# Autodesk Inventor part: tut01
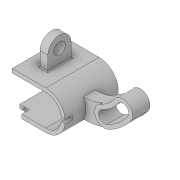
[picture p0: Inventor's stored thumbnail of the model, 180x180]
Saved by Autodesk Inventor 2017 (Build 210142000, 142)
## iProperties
Created: 2015-03
Part Number: tut01
Material: Generic
Document SubType Name: Modeling
Designer: Sandeep
Density: 1 g/cm^3
Appearance: Default
Author: Sandeep
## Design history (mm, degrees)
sketch "Sketch1"
  geometry: L1 (35, 20)-(0, 20); L2 (0, -20)-(35, -20); L3 (35, 16)-(0, 16); L4 (0, -16)-(35, -16); L5 (35, 16)-(35, 20); L6 (35, -16)-(35, -20); L7 (42.148, 0)-(-37.683, 0); A1 r 20 centre (0, 0) between (0, 20) and (0, -20); A2 r 16 centre (0, 0) between (0, 16) and (0, -16); 1 further point
  constraints: 14 end point, 4 point on circle, 2 centre point, 2 horizontal, 2 parallel, 2 tangent, 2 vertical, 1 coincident, 1 point on line, 3 other
  dimensions: "d0" = 35 distance of L2.start L2.end; "d1" = 20 radius of A1; "d2" = 4 distance between parallel lines of L2 L4
extrude "Extrusion1" new body sketch "Sketch1" stored distance "d3" = 55; taper "d4" = 0 deg
workplane "Work Plane1"
sketch "Sketch8"
  geometry: 1 further point
sketch "Sketch9"
  geometry: L1 (0, 55)-(0, 0) reference; L2 (0, 39.5)-(15, 39.5); L3 (15, 15.5)-(0, 15.5); L4 (0, 39.5)-(0, 15.5); L5 (-20, 27.5)-(24.854, 27.5); A1 r 12 centre (15, 27.5) between (15, 15.5) and (15, 39.5)
  constraints: 8 end point, 3 point on line, 2 horizontal, 2 point on circle, 2 tangent, 1 centre point, 1 collinear, 1 parallel
  dimensions: "d21" = 12 radius of A1; "d22" = 15 distance from line of L1 A1.centre
extrude "Extrusion5" join sketch "Sketch9" stored distance "d23" = 8; taper "d24" = 0 deg
sketch "Sketch10"
  geometry: C1 r 6 at (15, 27.5); A1 r 12 centre (15, 27.5) between (15, 15.5) and (15, 39.5) reference; 1 further point
  constraints: 1 centre point, 1 concentric
  dimensions: "d25" = 12 diameter of C1
extrude "Extrusion6" cut sketch "Sketch10" distance "d26" = 8; taper "d27" = 0 deg
fillet "Fillet1" dims "d28" = 1
sketch "Sketch11"
  geometry: L1 (15.875, -2)-(19.9, -2); L2 (15.875, 2)-(19.9, 2); L3 (0, 0)-(6.778, 0); L4 (-35, -20)-(-35, -16) reference; L5 (-35, -20)-(-25, -20); L6 (-25, -20)-(-25, -16); L7 (-25, -16)-(-35, -16); L8 (-35, -16)-(-35, -20); A1 r 16 centre (0, 0) between (0, -16) and (0, 16) reference; A2 r 20 centre (0, 0) between (0, -20) and (0, 20) reference; A3 r 20 centre (0, 0) between (19.9, -2) and (19.9, 2); A4 r 16 centre (0, 0) between (15.875, -2) and (15.875, 2); 1 further point
  constraints: 14 end point, 8 point on circle, 3 horizontal, 3 parallel, 2 centre point, 2 coincident, 1 perpendicular, 1 point on line, 1 other
  dimensions: "d30" = 2 distance from line of L3.end L2; "d31" = 10 distance between parallel lines of L4 L6
extrude "Extrusion7" cut sketch "Sketch11" distance "d32" = 8; taper "d33" = 0 deg
hole "Hole1" diameter "d36" = 2.5; stored, may be unused: countersink angle "d40" = 90 deg, drill point angle "d42" = 118 deg; dims "d34" = 2, "d37" = 6, "d38" = 4, "d39" = 2, "d41" = 4, "d44" = 5
sketch "Sketch12"
  geometry: L1 (0, 0)-(-32.975, 0); A1 r 20 centre (0, 0) between (-19.9, -2) and (0, -20) reference; A2 r 20 centre (0, 0) between (0, 20) and (-19.9, 2) reference; A3 r 20 centre (0, 0) between (0, 20) and (0, -20) reference; A4 r 10 centre (-61.269, 21.694) between (-53.311, 27.749) and (-69.227, 15.638); A5 r 45 centre (-17.5, 55) between (-53.311, 27.749) and (-17.32, 10); A6 r 65 centre (-17.5, 55) between (-69.227, 15.638) and (-17.321, -10); 1 further point
  constraints: 10 point on circle, 3 centre point, 2 end point, 2 tangent, 1 coincident, 1 horizontal
  dimensions: "d43" = 55 distance from line of A5.centre L1; "d45" = 17.5 horizontal distance of point (0, 0) A5.centre; "d46" = 20 diameter of A4; "d47" = 45 radius of A5; "d48" = 60 dimension on A6
extrude "Extrusion8" join sketch "Sketch12" stored distance "d49" = 12; taper "d50" = 0 deg
sketch "Sketch13"
  geometry: A1 r 10 centre (61.269, 21.694) between (69.227, 15.638) and (53.311, 27.749); A2 r 10 centre (61.269, 21.694) between (69.227, 15.638) and (53.311, 27.749) reference; A3 r 10 centre (41.857, 5.687) between (37.428, 14.653) and (46.286, -3.279); A4 r 45 centre (17.5, 55) between (37.428, 14.653) and (53.311, 27.749); A5 r 65 centre (17.5, 55) between (46.286, -3.279) and (69.227, 15.638); A6 r 65 centre (17.5, 55) between (17.321, -10) and (69.227, 15.638) reference; A7 r 45 centre (17.5, 55) between (17.32, 10) and (53.311, 27.749) reference; 2 further points
  constraints: 12 point on circle, 4 centre point, 3 tangent, 1 concentric
  dimensions: "d53" = 30 dimension on A5
extrude "Extrusion9" join sketch "Sketch13" distance "d54" = 3; taper "d55" = 0 deg
mirror "Mirror1"
sketch "Sketch14"
  geometry: A1 r 48.605 centre (21.694, 49.913) between (41.857, 5.687) and (61.269, 21.694); A2 r 54.605 centre (21.694, 49.913) between (44.346, 0.228) and (66.154, 18.21); A3 r 42.605 centre (21.694, 49.913) between (39.368, 11.147) and (56.383, 25.177); A4 r 6 centre (41.857, 5.687) between (39.368, 11.147) and (44.346, 0.228); A5 r 6 centre (61.269, 21.694) between (66.154, 18.21) and (56.383, 25.177); A6 r 10 centre (61.269, 21.694) between (69.227, 15.638) and (53.311, 27.749) reference; A7 r 10 centre (41.857, 5.687) between (37.428, 14.653) and (46.286, -3.279) reference; 1 further point
  constraints: 10 point on circle, 5 centre point, 4 tangent, 2 concentric
  dimensions: "d57" = 30 deg dimension on A1.centre A1.end A1.start; "d58" = 6 radius of A5
extrude "Extrusion10" cut sketch "Sketch14" distance "d59" = 46.25; taper "d60" = 0 deg
body "Solid1"
other parameters: "d20" = -17.5
